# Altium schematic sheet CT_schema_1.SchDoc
size 534 x 466 mm
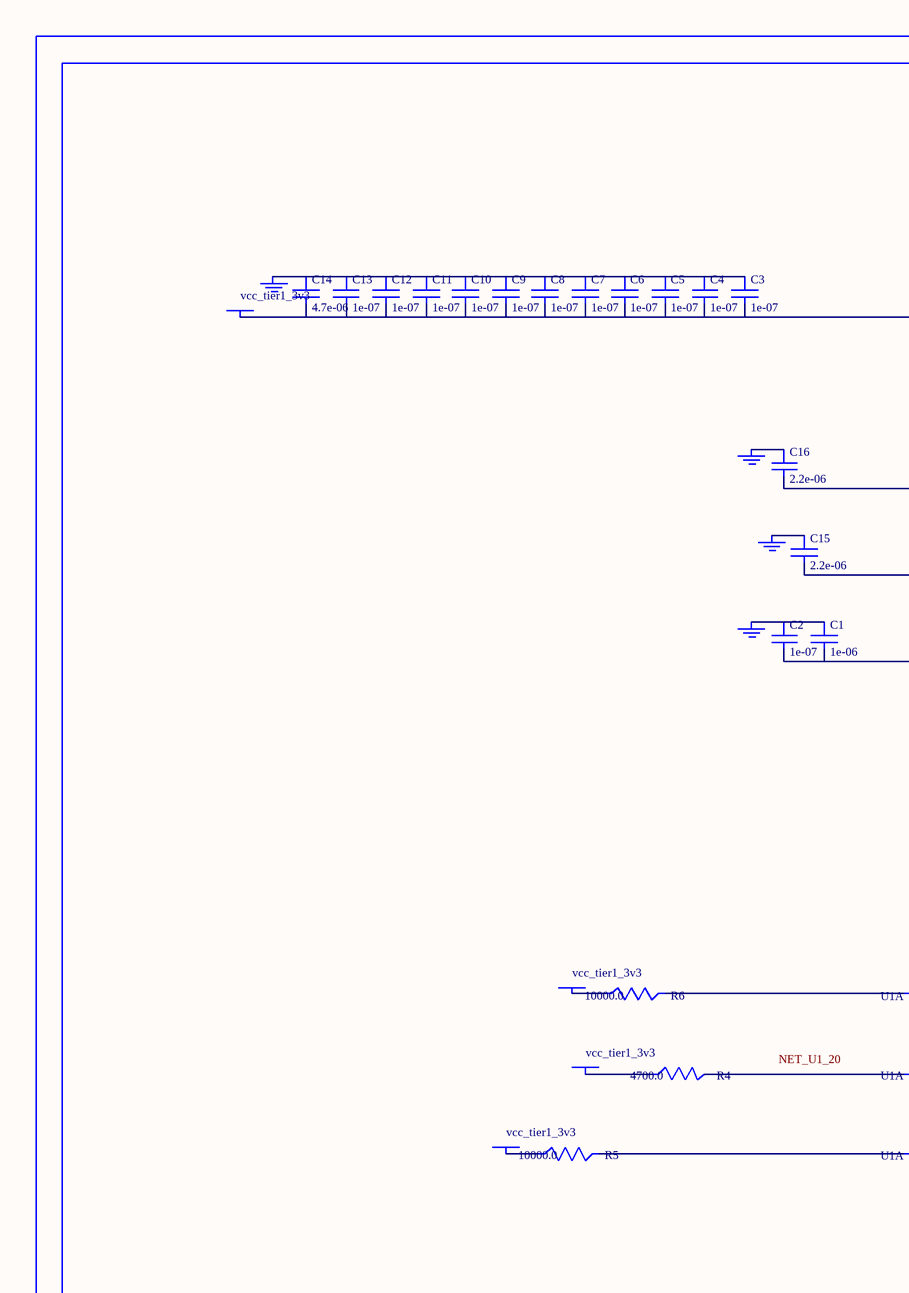
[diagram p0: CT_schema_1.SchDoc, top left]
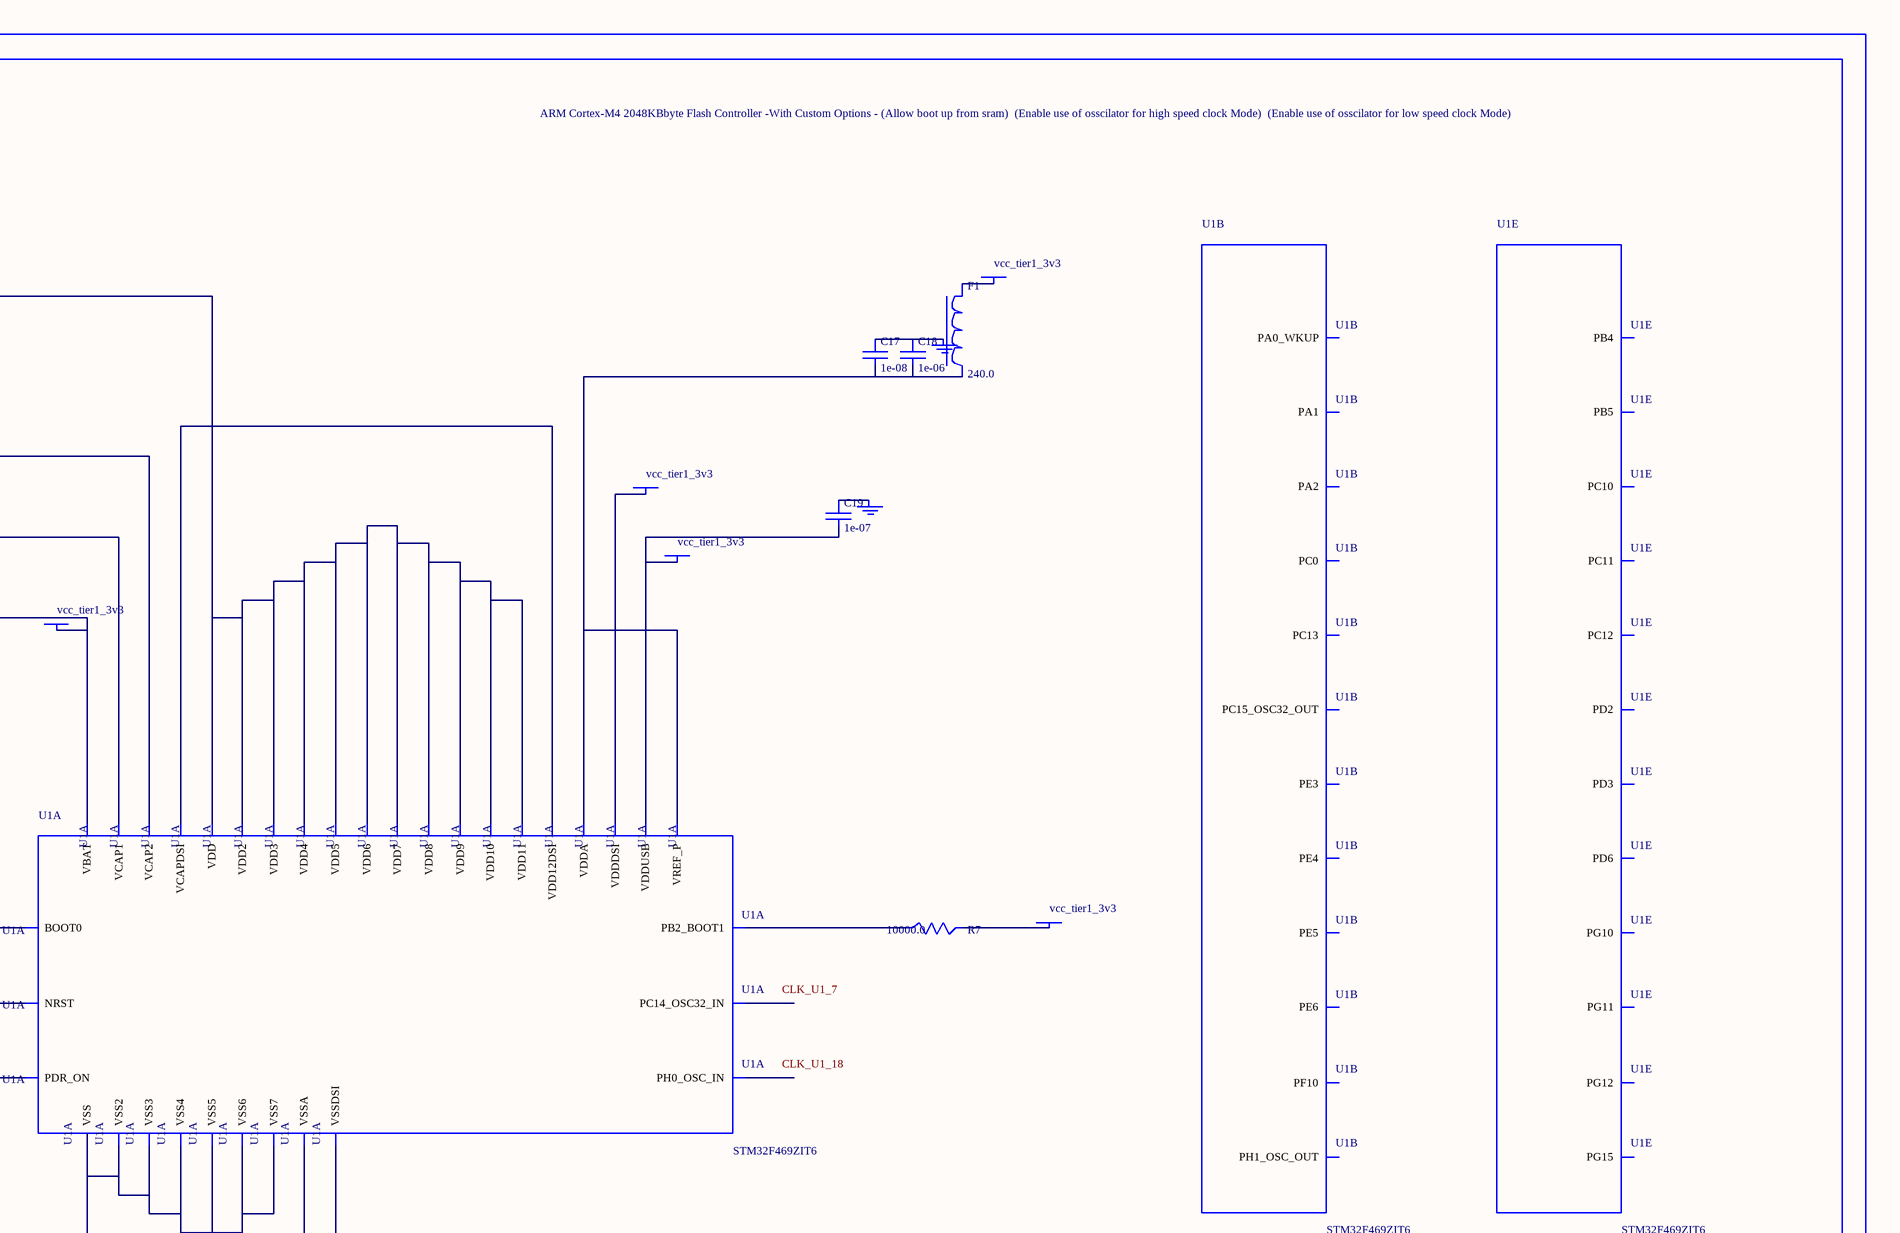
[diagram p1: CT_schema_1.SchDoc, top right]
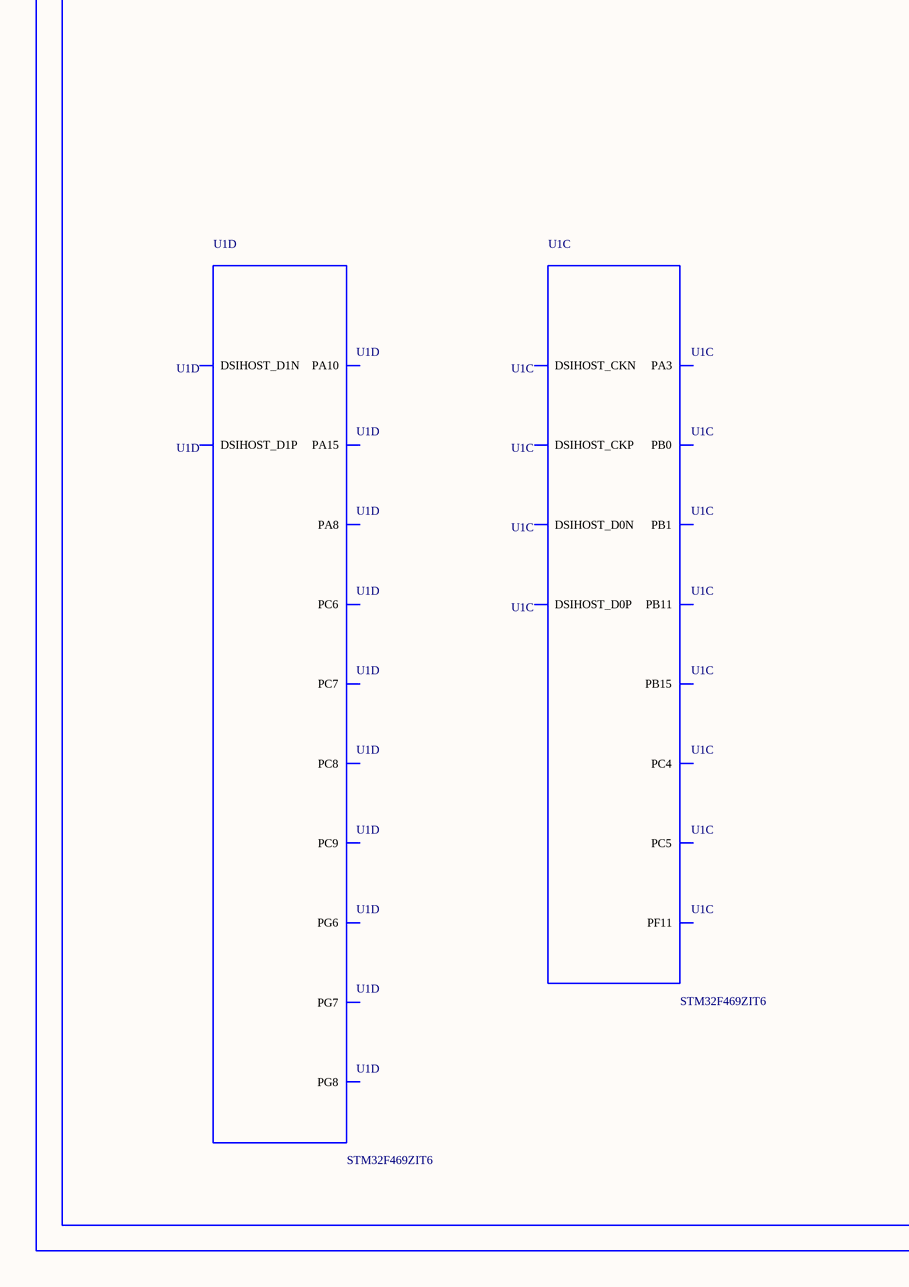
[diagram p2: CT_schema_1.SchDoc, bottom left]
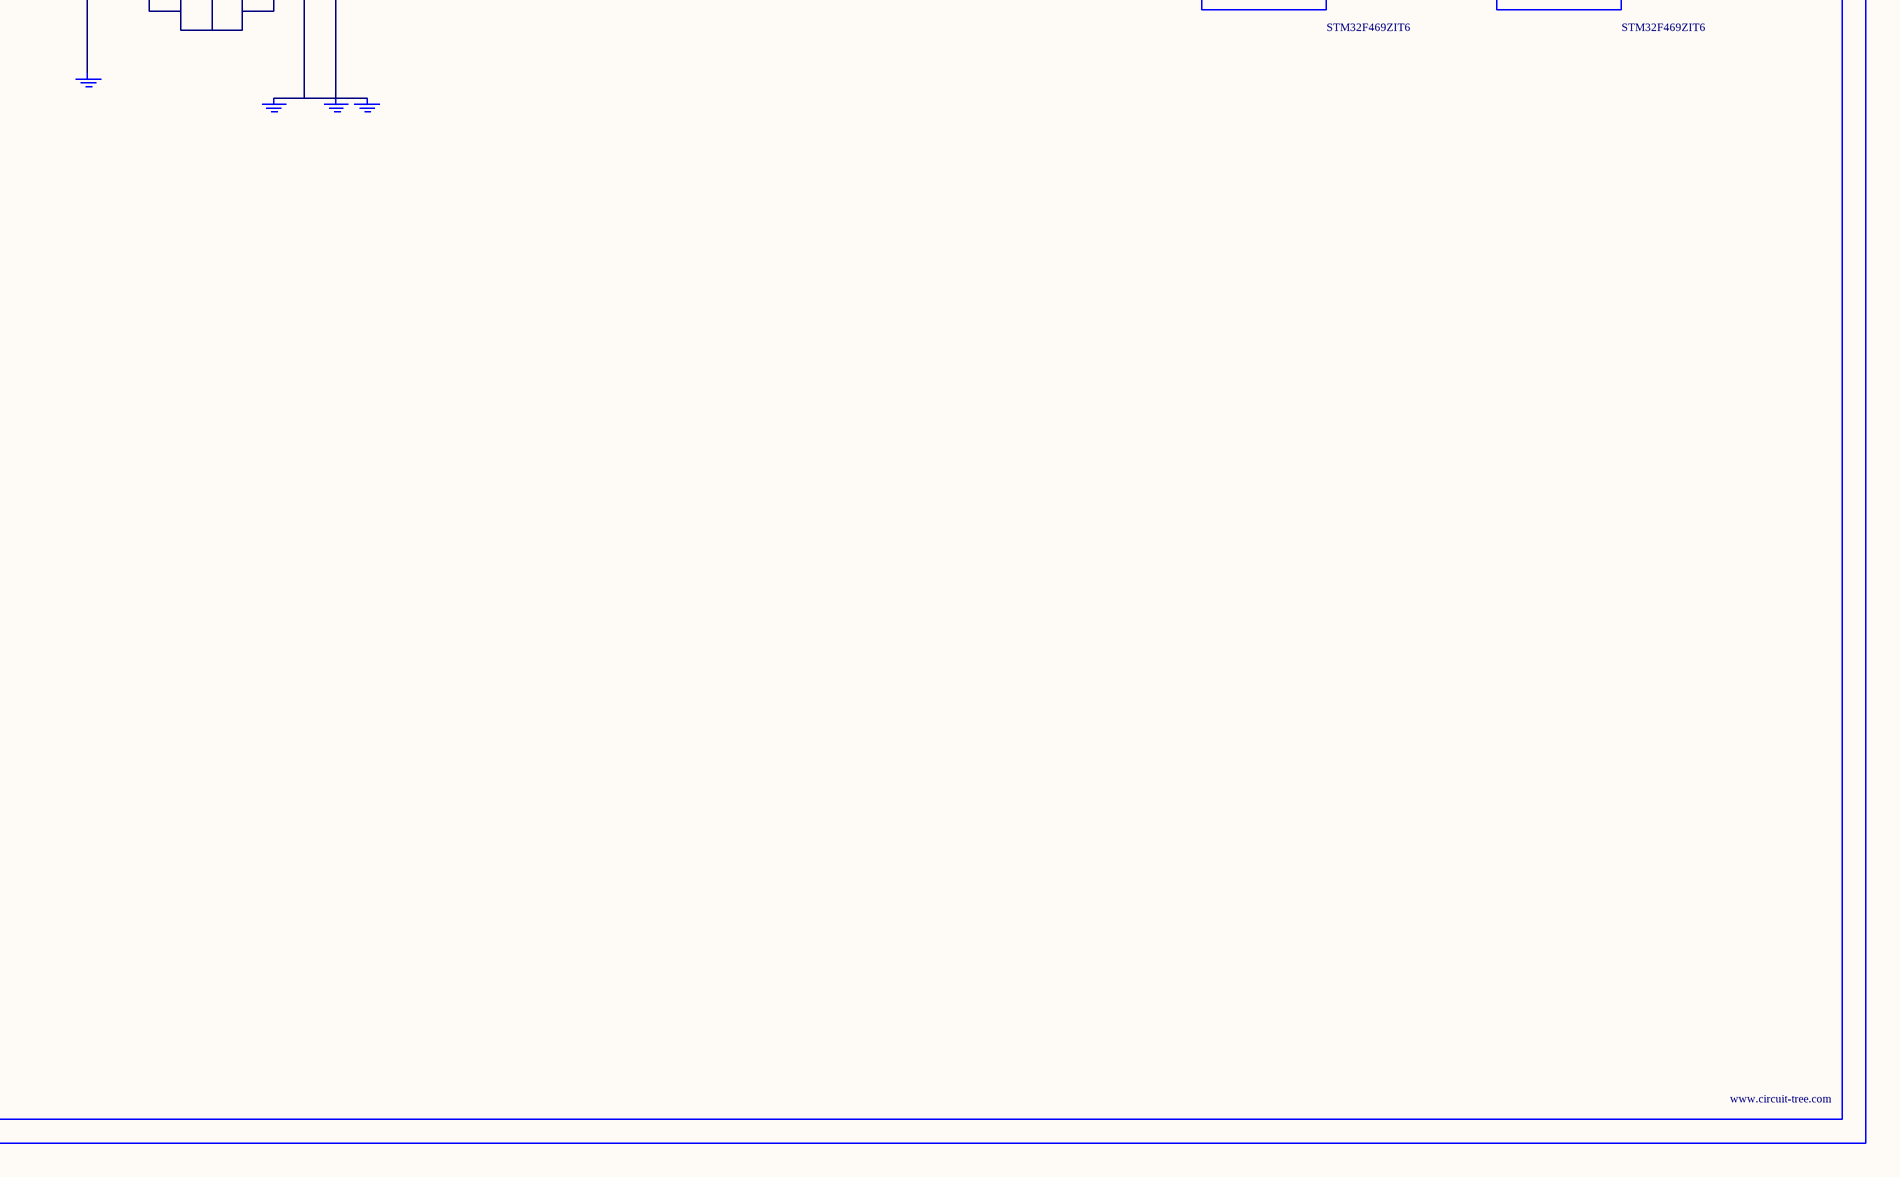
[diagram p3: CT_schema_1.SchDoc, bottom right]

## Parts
BORDER0  (no value)
C1  1e-06  [C0603]
C2  1e-07  [C0603]
C3  1e-07  [C0603]
C4  1e-07  [C0603]
C5  1e-07  [C0603]
C6  1e-07  [C0603]
C7  1e-07  [C0603]
C8  1e-07  [C0603]
C9  1e-07  [C0603]
C10  1e-07  [C0603]
C11  1e-07  [C0603]
C12  1e-07  [C0603]
C13  1e-07  [C0603]
C14  4.7e-06  [C0603]
C15  2.2e-06  [C0603]
C16  2.2e-06  [C0603]
C17  1e-08  [C0603]
C18  1e-06  [C0603]
C19  1e-07  [C0603]
F1  240.0  [L0603]
GND_INSTANCE_0_0  (no value)
GND_INSTANCE_0_1  (no value)
GND_INSTANCE_0_2  (no value)
GND_INSTANCE_0_3  (no value)
GND_INSTANCE_0_4  (no value)
GND_INSTANCE_0_5  (no value)
GND_INSTANCE_0_6  (no value)
GND_INSTANCE_0_7  (no value)
GND_INSTANCE_0_8  (no value)
GND_INSTANCE_0_9  (no value)
POWER_INSTANCE_0_0  vcc_tier1_3v3
POWER_INSTANCE_0_1  vcc_tier1_3v3
POWER_INSTANCE_0_2  vcc_tier1_3v3
POWER_INSTANCE_0_3  vcc_tier1_3v3
POWER_INSTANCE_0_4  vcc_tier1_3v3
POWER_INSTANCE_0_5  vcc_tier1_3v3
POWER_INSTANCE_0_6  vcc_tier1_3v3
POWER_INSTANCE_0_7  vcc_tier1_3v3
POWER_INSTANCE_0_8  vcc_tier1_3v3
R4  4700.0  [R0603]
R5  10000.0  [R0603]
R6  10000.0  [R0603]
R7  10000.0  [R0603]
U1  STM32F469ZIT6  [LQFP144]  (parts A,B,C,D,E of 14)

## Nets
NetC1_1: C1.1 C2.1 GND_INSTANCE_0_0.0(GND)
NetC1_2: C1.2 C2.2 POWER_INSTANCE_0_0.0(PWR) U1.5(VBAT)
NetC3_1: C3.1 C4.1 C5.1 C6.1 C7.1 C8.1 C9.1 C10.1 C11.1 C12.1 C13.1 C14.1 GND_INSTANCE_0_1.0(GND)
NetC3_2: C3.2 C4.2 C5.2 C6.2 C7.2 C8.2 C9.2 C10.2 C11.2 C12.2 C13.2 C14.2 POWER_INSTANCE_0_1.0(PWR) U1.16(VDD) U1.25(VDD2) U1.34(VDD3) U1.46(VDD4) U1.56(VDD5) U1.66(VDD6) U1.77(VDD7) U1.110(VDD8) U1.123(VDD9) U1.130(VDD10) U1.143(VDD11)
NetC15_1: C15.1 GND_INSTANCE_0_4.0(GND)
NetC15_2: C15.2 U1.65(VCAP1)
NetC16_1: C16.1 GND_INSTANCE_0_8.0(GND)
NetC16_2: C16.2 U1.108(VCAP2)
NetC17_1: C17.1 C18.1 GND_INSTANCE_0_3.0(GND)
NetC17_2: C17.2 C18.2 F1.2 U1.27(VREF_P) U1.28(VDDA)
NetC19_1: C19.1 GND_INSTANCE_0_7.0(GND)
NetC19_2: C19.2 POWER_INSTANCE_0_5.0(PWR) U1.97(VDDUSB)
NetF1_1: F1.1 POWER_INSTANCE_0_2.0(PWR)
NetGND_INSTANCE_0_2_0: GND_INSTANCE_0_2.0(GND) GND_INSTANCE_0_5.0(GND) GND_INSTANCE_0_6.0(GND) U1.26(VSSA) U1.84(VSSDSI)
NetGND_INSTANCE_0_9_0: GND_INSTANCE_0_9.0(GND) U1.15(VSS) U1.33(VSS2) U1.55(VSS3) U1.76(VSS4) U1.109(VSS5) U1.122(VSS6) U1.129(VSS7)
NetPOWER_INSTANCE_0_3_0: POWER_INSTANCE_0_3.0(PWR) R7.2
NetPOWER_INSTANCE_0_4_0: POWER_INSTANCE_0_4.0(PWR) U1.80(VDDDSI)
NetPOWER_INSTANCE_0_6_0: POWER_INSTANCE_0_6.0(PWR) R6.1
NetPOWER_INSTANCE_0_7_0: POWER_INSTANCE_0_7.0(PWR) R5.1
NetPOWER_INSTANCE_0_8_0: POWER_INSTANCE_0_8.0(PWR) R4.1
NetR4_2: R4.2 U1.20(NRST)
NetR5_2: R5.2 U1.142(PDR_ON)
NetR6_2: R6.2 U1.137(BOOT0)
NetR7_1: R7.1 U1.43(PB2_BOOT1)
NetU1_81: U1.81(VCAPDSI) U1.87(VDD12DSI)

Not connected (* = marked no-connect by the designer): U1 1(PE3) 2(PE4) 3(PE5) 4(PE6) 6(PC13) 7(PC14_OSC32_IN) 8(PC15_OSC32_OUT) 17(PF10) 18(PH0_OSC_IN) 19(PH1_OSC_OUT) 21(PC0) 29(PA0_WKUP) 30(PA1) 31(PA2) 32(PA3) 39(PC4) 40(PC5) 41(PB0) 42(PB1) 44(PF11) 64(PB11) 70(PB15) 82(DSIHOST_D0P) 83(DSIHOST_D0N) 85(DSIHOST_CKP) 86(DSIHOST_CKN) 88(DSIHOST_D1P) 89(DSIHOST_D1N) 94(PG6) 95(PG7) 96(PG8) 98(PC6) 99(PC7) 100(PC8) 101(PC9) 102(PA8) 104(PA10) 112(PA15) 113(PC10) 114(PC11) 115(PC12) 118(PD2) 119(PD3) 124(PD6) 126(PG10) 127(PG11) 128(PG12) 131(PG15) 133(PB4) 134(PB5)

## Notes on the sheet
- Labels drawn without touching a wire or pin: CLK_U1_7, CLK_U1_18, NET_U1_20

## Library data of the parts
BORDER0 = BORDER_PAGE0
C1 C18 = C0603C105K3RACTU
C2-C13 C19 = 06035C104K4Z2A
C14 = GRM188R6YA475KE15D
C15 C16 = C0603C225K8RACTU
C17 = 06035C103K4Z2A
F1 = Z0603C241ASMST
GND_INSTANCE_0_0-GND_INSTANCE_0_9 = GND
POWER_INSTANCE_0_0-POWER_INSTANCE_0_8 = PWR
R4 = RC0603JR-074K7L
R5-R7 = RC0603JR-0710KL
